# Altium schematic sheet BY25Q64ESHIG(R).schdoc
size 127 x 101 mm
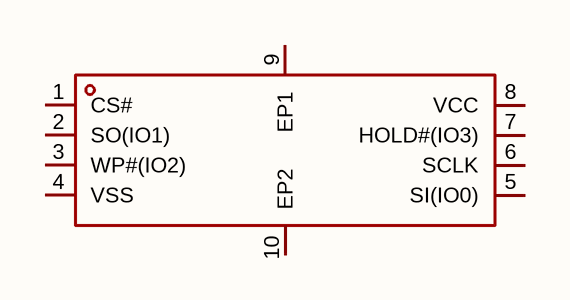
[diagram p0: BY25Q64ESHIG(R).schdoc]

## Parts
U?  by25q64eshig(r)  [USON-8_L4.0-W3.0-P0.80-BL_GD25Q32CNIGR]  (value not drawn)

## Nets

Not connected (* = marked no-connect by the designer): U? 1(CS#) 2(SO(IO1)) 3(WP#(IO2)) 4(VSS) 5(SI(IO0)) 6(SCLK) 7(HOLD#(IO3)) 8(VCC) 9(EP1) 10(EP2)

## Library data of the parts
U? = by25q64eshig(r): 接口类型:SPI;存储容量:64Mbit;时钟频率(fc):120MHz;; Manufacturer: BOYAMICRO(博雅); AddInBom: yes; ModelId: ce39ad9f02d04d848d7f2c3c3cc09f44; ModelName: USON-8_L4.0-W3.0-H0.6-P0.80-BL_GD25Q32CNIGR; ModelTransform: 118.8974,158.267,0,90,0,0,-0.002,0.002,0; Interface: SPI; Memory Size: 64Mbit; Clock Frequency: 120MHz; Voltage - Supply: 2.7V~3.6V; Standby Supply Current: 0.7uA; Program / Erase Cycles: 100000次; Page Programming Time (Tpp): 450us; Block Erase Time(tBE): 180ms; Data Retention - TDR (Year): 20年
